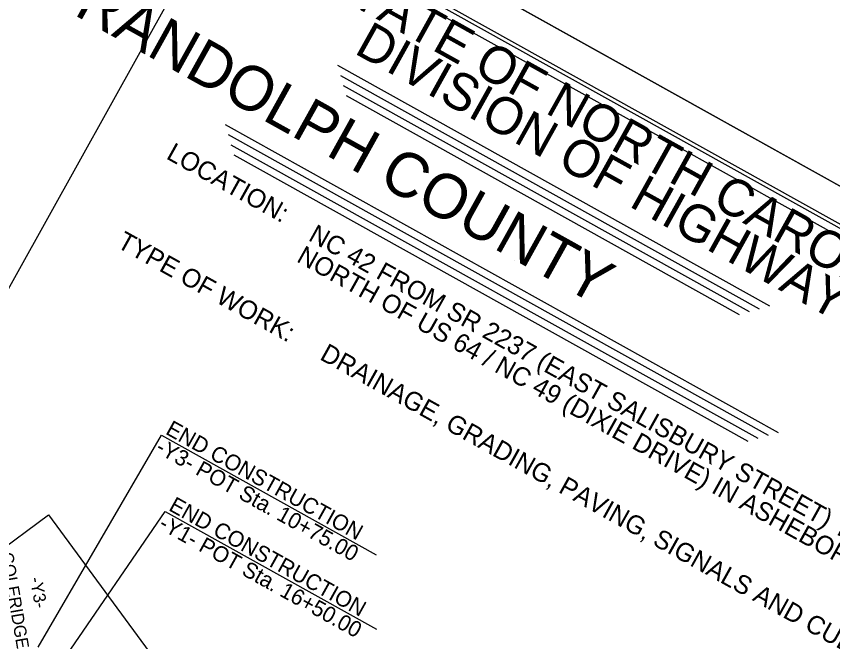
# Model space of a CAD drawing. Extents: x 1754939 to 1770240, y 706534 to 717510.
# Drawn here: x 1763770 to 1767067, y 712504 to 715030 of the extents above; entities that cross this region are included whole.
import ezdxf

# ---------------------------------------------------------------- set-up
doc = ezdxf.new("R2010")
doc.units = 0
for name, color, linetype in [('Culvert Barrel', 7, 'Continuous'), ('Culvert Wing', 7, 'Continuous'), ('ENG SEALS CELL', 7, 'Continuous'), ('Prop Conc Drive Radius Type', 7, 'Continuous'), ('Prop Lane Arrow CELL', 7, 'Continuous'), ('Prop Rem of Exist Asph Pvmt', 7, 'Continuous'), ('Prop SS Cut Line', 7, 'Continuous'), ('Scratch_Level_3', 7, 'Continuous'), ('Sheet PE Seal Cell', 7, 'Continuous')]:
    doc.layers.add(name, color=color, linetype=linetype)

msp = doc.modelspace()

# ---------------------------------------------------------------- linework, layer by layer
at = {"layer": 'Culvert Barrel'}
msp.add_line((1761412.2, 717510.1), (1770239.7, 712594.3), dxfattribs=at)
at = {"layer": 'Culvert Wing'}
msp.add_lwpolyline([(1770239.7, 712594.3), (1761412.2, 717510.1), (1758201.2, 711744), (1767028.7, 706828.1)], close=True, dxfattribs=at)
at = {"layer": 'ENG SEALS CELL'}
msp.add_lwpolyline([(1763819.2, 711353.8), (1763256.7, 712119.2), (1763567.1, 712347.6), (1763674.3, 712850.2), (1763900.7, 713016.1), (1764665.2, 711975.8), (1764374.3, 711762)], close=True, dxfattribs=at)
at = {"layer": 'Prop Conc Drive Radius Type'}
for p, q in [((1765067.5, 714832.1), (1766811.8, 713860.8)), ((1765079.1, 714791.4), (1766770.9, 713849.1)), ((1765090.7, 714750.5), (1766730.2, 713837.6)), ((1765102.3, 714709.7), (1766689.4, 713826)), ((1764613.9, 714593), (1766847, 713349.4)), ((1764625.6, 714552.2), (1766806.2, 713337.8)), ((1764637.1, 714511.3), (1766765.4, 713326.2)), ((1764648.8, 714470.6), (1766724.6, 713314.6))]:
    msp.add_line(p, q, dxfattribs=at)
for points in [[(1770025.3, 712542), (1762267, 716862.5)], [(1769984.4, 712530.4), (1762540.8, 716675.6)]]:
    msp.add_lwpolyline(points, dxfattribs=at)
at = {"layer": 'Prop Lane Arrow CELL'}
msp.add_lwpolyline([(1758334.8, 711823.6), (1767070.6, 706958.9), (1770150.6, 712489.7), (1761414.8, 717354.5), (1758334.8, 711823.6)], dxfattribs=at)
at = {"layer": 'Prop Rem of Exist Asph Pvmt'}
msp.add_line((1765782.1, 714044.8), (1765782.1, 714044.8), dxfattribs=at)
at = {"layer": 'Prop SS Cut Line'}
for p, q in [((1763857.8, 712482.2), (1764356.1, 713338.2)), ((1764356.1, 713338.2), (1765223.4, 712855.3)), ((1763934.8, 712394.1), (1764371.1, 713029.5)), ((1764371.1, 713029.5), (1765224.6, 712554.2))]:
    msp.add_line(p, q, dxfattribs=at)
at = {"layer": 'Sheet PE Seal Cell'}
msp.add_lwpolyline([(1762475.9, 716463.6), (1764515.4, 715327.8), (1763647.8, 713769.9), (1761608.3, 714905.6)], close=True, dxfattribs=at)

# ---------------------------------------------------------------- texts
at = {"layer": 'Prop Conc Drive Radius Type'}
for s, height, p in [('STATE OF NORTH CAROLINA', 149.999, (1764996.4, 715146)), ('DIVISION OF HIGHWAYS', 149.999, (1765130.6, 714882.5)), ('LOCATION: ', 75, (1764371.6, 714457.1)), ('TYPE OF WORK:', 75.001, (1764172.3, 714099.3))]:
    msp.add_text(s, height=height, rotation=330.8875, dxfattribs=at).set_placement(p)
at = {"layer": 'Prop SS Cut Line'}
for s, p in [('END CONSTRUCTION', (1764369, 713345.1)), ('-Y3- POT Sta. 10+75.00', (1764328.3, 713272)), ('END CONSTRUCTION', (1764381.7, 713036.7)), ('-Y1- POT Sta. 16+50.00', (1764341, 712963.7))]:
    msp.add_text(s, height=63.75, rotation=330.8875, dxfattribs=at).set_placement(p)
at = {"layer": 'Scratch_Level_3'}
for s, height, p in [('       RANDOLPH COUNTY       ', 180, (1763589.6, 715265.8)), ('NC 42 FROM SR 2237 (EAST SALISBURY STREET) TO ', 75.001, (1764945.9, 714127.1)), ('NORTH OF US 64 / NC 49 (DIXIE DRIVE) IN ASHEBORO', 75.001, (1764898.1, 714041.2)), ('DRAINAGE, GRADING, PAVING, SIGNALS AND CULVERTS', 75.001, (1764991.8, 713646.3))]:
    msp.add_text(s, height=height, rotation=330.8875, dxfattribs=at).set_placement(p)
at = {"layer": 'Sheet PE Seal Cell'}
for s, rotation, p in [('COLERIDGE ', 279.6489, (1763707.3, 712860.6)), ('-Y3-', 280.0243, (1763824.6, 712760.8))]:
    msp.add_text(s, height=50, rotation=rotation, dxfattribs=at).set_placement(p)

doc.saveas('drawing.dxf')
